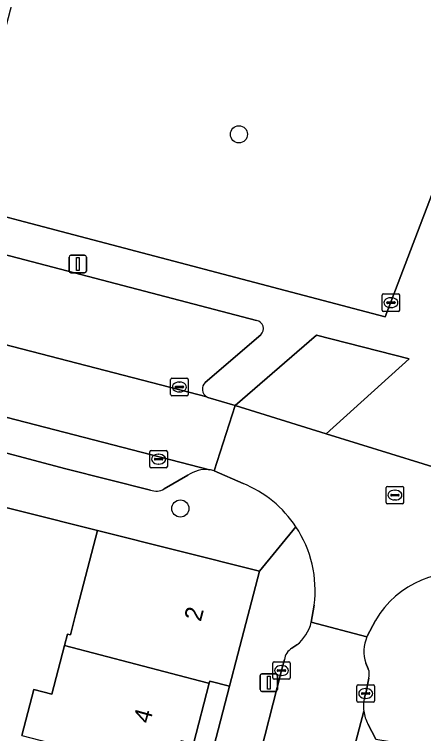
# Model space of a CAD drawing. Extents: x 163683 to 164494, y 382709 to 383872.
# Drawn here: x 164180.51 to 164203.92, y 383184.47 to 383225.65 of the extents above; entities that cross this region are included whole.
import ezdxf

# ---------------------------------------------------------------- set-up
doc = ezdxf.new("R2010")
doc.units = 0
for name, color, linetype in [('IMGEO_Boom', 7, 'Continuous'), ('IMGEO_Erf', 7, 'Continuous'), ('IMGEO_Groenvoorziening', 7, 'Continuous'), ('IMGEO_Kolk', 7, 'Continuous'), ('IMGEO_Lichtmast', 7, 'Continuous'), ('IMGEO_Muur', 7, 'Continuous'), ('IMGEO_Pand', 7, 'Continuous'), ('IMGEO_Pand_nummerreeks', 7, 'Continuous'), ('IMGEO_Parkeervlak_open', 7, 'Continuous'), ('IMGEO_Rijbaan_lokaal_open', 7, 'Continuous'), ('IMGEO_Rioolput', 7, 'Continuous'), ('IMGEO_Voetpad_open', 7, 'Continuous')]:
    doc.layers.add(name, color=color, linetype=linetype)

msp = doc.modelspace()

# ---------------------------------------------------------------- linework, layer by layer
at = {"layer": 'IMGEO_Boom'}
for centre in [(164193.357, 383218.784), (164190.006, 383197.355)]:
    msp.add_circle(centre, 0.489, dxfattribs=at)
at = {"layer": 'IMGEO_Erf'}
msp.add_lwpolyline([(164180.944, 383184.366), (164181.629, 383187), (164182.658, 383186.732), (164183.379, 383189.505), (164183.551, 383190.167), (164183.712, 383190.125), (164184.009, 383191.261), (164185.275, 383196.098), (164176.583, 383198.281), (164174.876, 383191.699), (164171.766, 383192.505), (164171.003, 383189.379), (164174.475, 383188.478), (164173.885, 383186.203), (164172.661, 383181.485)], dxfattribs=at)
msp.add_lwpolyline([(164192.826, 383187.181), (164191.684, 383187.478), (164191.651, 383187.35), (164190.752, 383183.877), (164190.046, 383184.06), (164189.546, 383182.128), (164189.063, 383180.265), (164189.769, 383180.082), (164188.78, 383176.264), (164187.826, 383172.58), (164187.12, 383172.763), (164186.601, 383170.759), (164186.138, 383168.968), (164186.844, 383168.785), (164185.839, 383164.904), (164184.903, 383161.292), (164184.197, 383161.475), (164183.658, 383159.39), (164183.215, 383157.68), (164183.921, 383157.497), (164182.985, 383153.885), (164184.107, 383153.593)], close=True, dxfattribs=at)
at = {"layer": 'IMGEO_Groenvoorziening'}
msp.add_lwpolyline([(164211.56, 383234.158), (164211.902, 383235.056), (164184.544, 383242.181), (164182.325, 383233.76), (164178.067, 383217.602), (164176.82, 383217.925), (164176.086, 383215.093), (164178.697, 383214.405), (164180.721, 383213.871), (164201.717, 383208.336), (164202.06, 383209.236)], close=True, dxfattribs=at)
at = {"layer": 'IMGEO_Kolk'}
for p, q in [((164201.553, 383208.718), (164201.553, 383209.57)), ((164201.628, 383209.644), (164202.48, 383209.644)), ((164202.041, 383209.424), (164202.066, 383209.424)), ((164202.554, 383209.57), (164202.554, 383208.718)), ((164201.812, 383209.138), (164201.812, 383209.15)), ((164202.25, 383209.101), (164201.852, 383209.101)), ((164201.855, 383209.187), (164202.253, 383209.187)), ((164202.064, 383208.864), (164202.039, 383208.864)), ((164202.296, 383209.15), (164202.296, 383209.138)), ((164202.48, 383208.644), (164201.628, 383208.644)), ((164189.452, 383203.888), (164189.452, 383204.74)), ((164189.527, 383204.814), (164190.379, 383204.814)), ((164190.453, 383204.74), (164190.453, 383203.888)), ((164189.711, 383204.308), (164189.711, 383204.32)), ((164189.754, 383204.357), (164190.152, 383204.357)), ((164189.94, 383204.594), (164189.965, 383204.594)), ((164190.195, 383204.32), (164190.195, 383204.308)), ((164190.149, 383204.271), (164189.751, 383204.271)), ((164189.963, 383204.034), (164189.938, 383204.034)), ((164190.379, 383203.814), (164189.527, 383203.814)), ((164188.263, 383199.758), (164188.263, 383200.61)), ((164188.338, 383200.684), (164189.19, 383200.684)), ((164189.264, 383200.61), (164189.264, 383199.758)), ((164188.565, 383200.227), (164188.963, 383200.227)), ((164188.751, 383200.464), (164188.776, 383200.464)), ((164188.522, 383200.178), (164188.522, 383200.19)), ((164188.96, 383200.141), (164188.562, 383200.141)), ((164188.774, 383199.904), (164188.749, 383199.904)), ((164189.006, 383200.19), (164189.006, 383200.178)), ((164189.19, 383199.684), (164188.338, 383199.684)), ((164195.29, 383187.652), (164195.29, 383188.504)), ((164195.365, 383188.578), (164196.217, 383188.578)), ((164195.778, 383188.358), (164195.803, 383188.358)), ((164196.291, 383188.504), (164196.291, 383187.652)), ((164195.549, 383188.072), (164195.549, 383188.084)), ((164195.987, 383188.035), (164195.589, 383188.035)), ((164195.592, 383188.121), (164195.99, 383188.121)), ((164196.033, 383188.084), (164196.033, 383188.072)), ((164196.217, 383187.578), (164195.365, 383187.578)), ((164195.801, 383187.798), (164195.776, 383187.798)), ((164200.109, 383186.338), (164200.109, 383187.19)), ((164200.184, 383187.264), (164201.036, 383187.264)), ((164200.597, 383187.044), (164200.622, 383187.044)), ((164201.11, 383187.19), (164201.11, 383186.338)), ((164200.368, 383186.758), (164200.368, 383186.77)), ((164200.806, 383186.721), (164200.408, 383186.721)), ((164200.411, 383186.807), (164200.809, 383186.807)), ((164200.852, 383186.77), (164200.852, 383186.758)), ((164201.036, 383186.264), (164200.184, 383186.264)), ((164200.62, 383186.484), (164200.595, 383186.484))]:
    msp.add_line(p, q, dxfattribs=at)
for points in [[(164201.553, 383208.718), (164201.553, 383209.57)], [(164201.628, 383209.644), (164202.48, 383209.644)], [(164202.554, 383209.57), (164202.554, 383208.718)], [(164202.48, 383208.644), (164201.628, 383208.644)], [(164189.452, 383203.888), (164189.452, 383204.74)], [(164189.527, 383204.814), (164190.379, 383204.814)], [(164190.453, 383204.74), (164190.453, 383203.888)], [(164190.379, 383203.814), (164189.527, 383203.814)], [(164188.263, 383199.758), (164188.263, 383200.61)], [(164188.338, 383200.684), (164189.19, 383200.684)], [(164189.264, 383200.61), (164189.264, 383199.758)], [(164189.19, 383199.684), (164188.338, 383199.684)], [(164195.29, 383187.652), (164195.29, 383188.504)], [(164195.365, 383188.578), (164196.217, 383188.578)], [(164196.291, 383188.504), (164196.291, 383187.652)], [(164196.217, 383187.578), (164195.365, 383187.578)], [(164200.109, 383186.338), (164200.109, 383187.19)], [(164200.184, 383187.264), (164201.036, 383187.264)], [(164201.11, 383187.19), (164201.11, 383186.338)], [(164201.036, 383186.264), (164200.184, 383186.264)]]:
    msp.add_lwpolyline(points, dxfattribs=at)
for centre, radius, start, end in [((164201.63, 383209.568), 0.0765, 91.552, 178.448), ((164201.63, 383209.568), 0.0765, 91.552, 178.448), ((164202.478, 383209.568), 0.0765, 1.552, 88.448), ((164202.478, 383209.568), 0.0765, 1.552, 88.448), ((164201.852, 383209.147), 0.0403, 85.8775, 175.7526), ((164201.849, 383209.137), 0.0366, 178.938, 274.7102), ((164202.253, 383209.144), 0.043, 264.8664, 352.4533), ((164202.257, 383209.149), 0.0386, 1.7309, 96.639), ((164201.63, 383208.72), 0.0765, 181.552, 268.448), ((164201.63, 383208.72), 0.0765, 181.552, 268.448), ((164202.478, 383208.72), 0.0765, 271.552, 358.448), ((164202.478, 383208.72), 0.0765, 271.552, 358.448), ((164189.529, 383204.738), 0.0765, 91.552, 178.448), ((164189.529, 383204.738), 0.0765, 91.552, 178.448), ((164190.377, 383204.738), 0.0765, 1.552, 88.448), ((164190.377, 383204.738), 0.0765, 1.552, 88.448), ((164189.751, 383204.317), 0.0403, 85.8775, 175.7526), ((164190.156, 383204.319), 0.0386, 1.7309, 96.639), ((164189.748, 383204.307), 0.0366, 178.938, 274.7102), ((164190.152, 383204.314), 0.043, 264.8664, 352.4533), ((164189.529, 383203.89), 0.0765, 181.552, 268.448), ((164189.529, 383203.89), 0.0765, 181.552, 268.448), ((164190.377, 383203.89), 0.0765, 271.552, 358.448), ((164190.377, 383203.89), 0.0765, 271.552, 358.448), ((164188.34, 383200.608), 0.0765, 91.552, 178.448), ((164188.34, 383200.608), 0.0765, 91.552, 178.448), ((164189.188, 383200.608), 0.0765, 1.552, 88.448), ((164189.188, 383200.608), 0.0765, 1.552, 88.448), ((164188.562, 383200.187), 0.0403, 85.8775, 175.7526), ((164188.967, 383200.189), 0.0386, 1.7309, 96.639), ((164188.559, 383200.177), 0.0366, 178.938, 274.7102), ((164188.963, 383200.184), 0.043, 264.8664, 352.4533), ((164188.34, 383199.76), 0.0765, 181.552, 268.448), ((164188.34, 383199.76), 0.0765, 181.552, 268.448), ((164189.188, 383199.76), 0.0765, 271.552, 358.448), ((164189.188, 383199.76), 0.0765, 271.552, 358.448), ((164195.367, 383188.502), 0.0765, 91.552, 178.448), ((164195.367, 383188.502), 0.0765, 91.552, 178.448), ((164196.215, 383188.502), 0.0765, 1.552, 88.448), ((164196.215, 383188.502), 0.0765, 1.552, 88.448), ((164195.589, 383188.081), 0.0403, 85.8775, 175.7526), ((164195.586, 383188.071), 0.0366, 178.938, 274.7102), ((164195.99, 383188.078), 0.043, 264.8664, 352.4533), ((164195.994, 383188.083), 0.0386, 1.7309, 96.639), ((164195.367, 383187.654), 0.0765, 181.552, 268.448), ((164195.367, 383187.654), 0.0765, 181.552, 268.448), ((164196.215, 383187.654), 0.0765, 271.552, 358.448), ((164196.215, 383187.654), 0.0765, 271.552, 358.448), ((164200.186, 383187.188), 0.0765, 91.552, 178.448), ((164200.186, 383187.188), 0.0765, 91.552, 178.448), ((164201.034, 383187.188), 0.0765, 1.552, 88.448), ((164201.034, 383187.188), 0.0765, 1.552, 88.448), ((164200.408, 383186.767), 0.0403, 85.8775, 175.7526), ((164200.405, 383186.757), 0.0366, 178.938, 274.7102), ((164200.809, 383186.764), 0.043, 264.8664, 352.4533), ((164200.813, 383186.769), 0.0386, 1.7309, 96.639), ((164200.186, 383186.34), 0.0765, 181.552, 268.448), ((164200.186, 383186.34), 0.0765, 181.552, 268.448), ((164201.034, 383186.34), 0.0765, 271.552, 358.448), ((164201.034, 383186.34), 0.0765, 271.552, 358.448)]:
    msp.add_arc(centre, radius, start, end, dxfattribs=at)
for centre, major_axis, ratio, start_param, end_param in [((164202.04, 383209.144), (-0.387, 0.002), 0.722429, 4.712389, 7.853982), ((164202.065, 383209.144), (-0.39, 0.002), 0.717154, 1.570796, 4.712389), ((164189.939, 383204.314), (-0.387, 0.002), 0.722429, 4.712389, 7.853982), ((164189.964, 383204.314), (-0.39, 0.002), 0.717154, 1.570796, 4.712389), ((164188.75, 383200.184), (-0.387, 0.002), 0.722429, 4.712389, 7.853982), ((164188.775, 383200.184), (-0.39, 0.002), 0.717154, 1.570796, 4.712389), ((164195.777, 383188.078), (-0.387, 0.002), 0.722429, 4.712389, 7.853982), ((164195.802, 383188.078), (-0.39, 0.002), 0.717154, 1.570796, 4.712389), ((164200.596, 383186.764), (-0.387, 0.002), 0.722429, 4.712389, 7.853982), ((164200.621, 383186.764), (-0.39, 0.002), 0.717154, 1.570796, 4.712389)]:
    msp.add_ellipse(centre, major_axis=major_axis, ratio=ratio, start_param=start_param, end_param=end_param, dxfattribs=at)
at = {"layer": 'IMGEO_Lichtmast'}
for p, q in [((164183.639, 383210.956), (164183.639, 383211.756)), ((164183.639, 383211.756), (164183.639, 383210.956)), ((164183.739, 383211.856), (164184.529, 383211.856)), ((164184.529, 383211.856), (164183.739, 383211.856)), ((164184.629, 383211.756), (164184.629, 383210.956)), ((164184.629, 383210.956), (164184.629, 383211.756)), ((164184.529, 383210.856), (164183.739, 383210.856)), ((164183.739, 383210.856), (164184.529, 383210.856)), ((164194.667, 383187.885), (164195.457, 383187.885)), ((164195.457, 383187.885), (164194.667, 383187.885)), ((164194.567, 383186.985), (164194.567, 383187.785)), ((164194.567, 383187.785), (164194.567, 383186.985)), ((164195.557, 383187.785), (164195.557, 383186.985)), ((164195.557, 383186.985), (164195.557, 383187.785)), ((164195.457, 383186.885), (164194.667, 383186.885)), ((164194.667, 383186.885), (164195.457, 383186.885))]:
    msp.add_line(p, q, dxfattribs=at)
for points in [[(164184.059, 383211.731), (164184.209, 383211.731), (164184.209, 383210.981), (164184.059, 383210.981), (164184.059, 383211.731)], [(164194.987, 383187.76), (164195.137, 383187.76), (164195.137, 383187.01), (164194.987, 383187.01), (164194.987, 383187.76)]]:
    msp.add_lwpolyline(points, dxfattribs=at)
for centre, start, end in [((164183.739, 383211.756), 90, 180), ((164183.739, 383211.756), 90, 180), ((164184.529, 383211.756), 0, 90), ((164184.529, 383211.756), 360, 90), ((164183.739, 383210.956), 180, 270), ((164183.739, 383210.956), 180, 270), ((164184.529, 383210.956), 270, 0), ((164184.529, 383210.956), 270, 0), ((164194.667, 383187.785), 90, 180), ((164194.667, 383187.785), 90, 180), ((164195.457, 383187.785), 0, 90), ((164195.457, 383187.785), 360, 90), ((164194.667, 383186.985), 180, 270), ((164194.667, 383186.985), 180, 270), ((164195.457, 383186.985), 270, 0), ((164195.457, 383186.985), 270, 0)]:
    msp.add_arc(centre, 0.1, start, end, dxfattribs=at)
at = {"layer": 'IMGEO_Muur'}
msp.add_lwpolyline([(164176.583, 383198.281), (164185.275, 383196.098)], dxfattribs=at)
at = {"layer": 'IMGEO_Pand'}
for points in [[(164183.379, 383189.505), (164191.535, 383187.38), (164191.651, 383187.35), (164191.684, 383187.478), (164192.826, 383187.181), (164193.301, 383189.011), (164194.537, 383193.772), (164185.275, 383196.098), (164184.009, 383191.261), (164183.712, 383190.125), (164183.551, 383190.167)], [(164180.944, 383184.366), (164189.546, 383182.128), (164190.046, 383184.06), (164190.752, 383183.877), (164191.651, 383187.35), (164191.535, 383187.38), (164183.379, 383189.505), (164182.658, 383186.732), (164181.629, 383187)]]:
    msp.add_lwpolyline(points, close=True, dxfattribs=at)
at = {"layer": 'IMGEO_Parkeervlak_open'}
for points in [[(164194.367, 383208.132), (164180.308, 383211.798), (164179.296, 383212.06)], [(164174.565, 383208.139), (164191.519, 383203.748)], [(164191.428, 383204.572), (164194.606, 383207.31)], [(164200.503, 383185.752), (164195.035, 383165.03)], [(164201.195, 383184.141), (164200.736, 383185.025)]]:
    msp.add_lwpolyline(points, dxfattribs=at)
msp.add_lwpolyline([(164193.144, 383203.259), (164198.344, 383201.637), (164203.1, 383205.927), (164197.787, 383207.289)], close=True, dxfattribs=at)
for centre, radius, start, end in [((164194.274, 383207.659), 0.482, 313.5755, 78.8485), ((164191.781, 383204.194), 0.517, 133.058, 239.5461), ((164202.635, 383186.034), 2.15, 187.5445, 207.9963)]:
    msp.add_arc(centre, radius, start, end, dxfattribs=at)
at = {"layer": 'IMGEO_Rijbaan_lokaal_open'}
for points in [[(164191.674, 383199.573), (164137.37, 383213.628), (164065.47, 383232.191)], [(164065.47, 383232.191), (164137.37, 383213.628), (164191.674, 383199.573)], [(164067.443, 383229.643), (164078.076, 383226.898), (164083.857, 383225.406), (164123.682, 383215.09), (164133.127, 383212.643), (164172.83, 383202.406), (164178.631, 383200.91), (164182.52, 383199.875), (164183.453, 383199.638), (164188.301, 383198.414)], [(164191.936, 383199.519), (164193.144, 383203.259), (164191.577, 383203.719), (164191.548, 383203.733), (164191.519, 383203.748), (164174.565, 383208.139)], [(164212.176, 383197.307), (164211.291, 383197.629), (164198.344, 383201.637), (164193.144, 383203.259), (164191.936, 383199.519), (164193.591, 383198.789)], [(164189.075, 383198.48), (164190.439, 383199.257)], [(164197.667, 383191.827), (164197.5, 383190.84), (164200.68, 383190.002), (164200.702, 383190.05), (164201.176, 383190.951)], [(164200.68, 383190.002), (164197.5, 383190.84)], [(164196.666, 383189.542), (164196.387, 383189.35)], [(164195.962, 383188.713), (164195.791, 383188.078), (164194.358, 383182.464), (164189.313, 383162.614), (164185.499, 383148.358), (164185.032, 383146.554)], [(164200.761, 383188.179), (164200.622, 383188.506)], [(164200.542, 383186.562), (164200.61, 383186.764), (164200.79, 383187.637)], [(164185.239, 383144.22), (164185.117, 383143.761), (164188.959, 383142.625), (164189.357, 383144.074), (164193.665, 383159.724), (164194.577, 383163.198), (164195.035, 383165.03), (164200.503, 383185.752)]]:
    msp.add_lwpolyline(points, dxfattribs=at)
for centre, radius, start, end in [((164191.457, 383197.851), 1.736, 82.8053, 125.8994), ((164191.451, 383197.83), 1.757, 73.9877, 82.7204), ((164191.101, 383192.656), 6.619, 33.4661, 67.9036), ((164188.621, 383199.232), 0.878, 248.6214, 301.1264), ((164191.107, 383192.659), 6.612, 352.77, 33.4714), ((164205.874, 383188.236), 5.426, 74.9953, 149.9735), ((164195.189, 383191.408), 2.379, 308.3597, 346.1966), ((164202.546, 383189.181), 2.039, 156.2366, 199.3229), ((164196.818, 383188.602), 0.864, 119.9723, 172.6061), ((164199.919, 383187.862), 0.9, 345.5048, 20.6207), ((164202.426, 383186.065), 1.948, 165.2314, 189.2555)]:
    msp.add_arc(centre, radius, start, end, dxfattribs=at)
at = {"layer": 'IMGEO_Rioolput'}
for p, q in [((164201.782, 383197.698), (164201.782, 383198.55)), ((164201.857, 383198.624), (164202.709, 383198.624)), ((164202.783, 383198.55), (164202.783, 383197.698)), ((164202.084, 383198.167), (164202.482, 383198.167)), ((164202.27, 383198.404), (164202.295, 383198.404)), ((164202.041, 383198.118), (164202.041, 383198.13)), ((164202.479, 383198.081), (164202.081, 383198.081)), ((164202.293, 383197.844), (164202.268, 383197.844)), ((164202.525, 383198.13), (164202.525, 383198.118)), ((164202.709, 383197.624), (164201.857, 383197.624))]:
    msp.add_line(p, q, dxfattribs=at)
for points in [[(164201.782, 383197.698), (164201.782, 383198.55)], [(164201.857, 383198.624), (164202.709, 383198.624)], [(164202.783, 383198.55), (164202.783, 383197.698)], [(164202.709, 383197.624), (164201.857, 383197.624)]]:
    msp.add_lwpolyline(points, dxfattribs=at)
for centre, radius, start, end in [((164201.859, 383198.548), 0.0765, 91.552, 178.448), ((164201.859, 383198.548), 0.0765, 91.552, 178.448), ((164202.707, 383198.548), 0.0765, 1.552, 88.448), ((164202.707, 383198.548), 0.0765, 1.552, 88.448), ((164202.081, 383198.127), 0.0403, 85.8775, 175.7526), ((164202.486, 383198.129), 0.0386, 1.7309, 96.639), ((164202.078, 383198.117), 0.0366, 178.938, 274.7102), ((164202.482, 383198.124), 0.043, 264.8664, 352.4533), ((164201.859, 383197.7), 0.0765, 181.552, 268.448), ((164201.859, 383197.7), 0.0765, 181.552, 268.448), ((164202.707, 383197.7), 0.0765, 271.552, 358.448), ((164202.707, 383197.7), 0.0765, 271.552, 358.448)]:
    msp.add_arc(centre, radius, start, end, dxfattribs=at)
for centre, major_axis, ratio, start_param, end_param in [((164202.269, 383198.124), (-0.387, 0.002), 0.722429, 4.712389, 7.853982), ((164202.294, 383198.124), (-0.39, 0.002), 0.717154, 1.570796, 4.712389)]:
    msp.add_ellipse(centre, major_axis=major_axis, ratio=ratio, start_param=start_param, end_param=end_param, dxfattribs=at)
at = {"layer": 'IMGEO_Voetpad_open'}
for points in [[(164211.56, 383234.158), (164202.06, 383209.236), (164201.717, 383208.336), (164180.721, 383213.871), (164178.697, 383214.405), (164176.086, 383215.093), (164174.958, 383210.745), (164163.56, 383213.701), (164165.194, 383220.005), (164164.803, 383220.106), (164165.555, 383223.008)], [(164188.301, 383198.414), (164183.453, 383199.638), (164182.52, 383199.875), (164178.631, 383200.91), (164178.343, 383199.742), (164172.528, 383201.19), (164172.83, 383202.406), (164133.127, 383212.643)], [(164179.296, 383212.06), (164180.308, 383211.798), (164194.367, 383208.132)], [(164131.207, 383210.146), (164165.211, 383201.212), (164165.276, 383201.461), (164171.86, 383199.754), (164171.782, 383199.454), (164173.473, 383199.087), (164173.798, 383199.003), (164176.279, 383198.36), (164176.583, 383198.281), (164185.275, 383196.098), (164194.537, 383193.772), (164196.623, 383196.306)], [(164194.606, 383207.31), (164191.428, 383204.572)], [(164191.519, 383203.748), (164191.548, 383203.733), (164191.577, 383203.719), (164193.144, 383203.259), (164197.787, 383207.289), (164203.1, 383205.927), (164198.344, 383201.637), (164211.291, 383197.629), (164212.176, 383197.307), (164217.636, 383195.693), (164217.81, 383195.654)], [(164193.591, 383198.789), (164191.936, 383199.519)], [(164190.439, 383199.257), (164189.075, 383198.48)], [(164196.623, 383196.306), (164194.537, 383193.772), (164193.301, 383189.011), (164192.826, 383187.181), (164184.107, 383153.593), (164184.067, 383153.438), (164182.395, 383147.001), (164181.718, 383144.288)], [(164197.5, 383190.84), (164197.667, 383191.827)], [(164201.176, 383190.951), (164200.702, 383190.05), (164200.68, 383190.002)], [(164196.387, 383189.35), (164196.666, 383189.542)], [(164194.358, 383182.464), (164195.791, 383188.078), (164195.962, 383188.713)], [(164200.622, 383188.506), (164200.761, 383188.179)], [(164200.79, 383187.637), (164200.61, 383186.764), (164200.542, 383186.562)], [(164200.736, 383185.025), (164201.195, 383184.141), (164203.756, 383183.734)]]:
    msp.add_lwpolyline(points, dxfattribs=at)
for centre, radius, start, end in [((164194.274, 383207.659), 0.482, 313.5755, 78.8485), ((164191.781, 383204.194), 0.517, 133.058, 239.5461), ((164191.457, 383197.851), 1.736, 82.8053, 125.8994), ((164191.451, 383197.83), 1.757, 73.9877, 82.7204), ((164191.101, 383192.656), 6.619, 33.4661, 67.9036), ((164188.621, 383199.232), 0.878, 248.6214, 301.1264), ((164191.107, 383192.659), 6.612, 352.77, 33.4714), ((164205.874, 383188.236), 5.426, 74.9953, 149.9735), ((164195.189, 383191.408), 2.379, 308.3597, 346.1966), ((164202.546, 383189.181), 2.039, 156.2366, 199.3229), ((164196.818, 383188.602), 0.864, 119.9723, 172.6061), ((164199.919, 383187.862), 0.9, 345.5048, 20.6207), ((164202.426, 383186.065), 1.948, 165.2314, 189.2555), ((164202.635, 383186.034), 2.15, 187.5445, 207.9963)]:
    msp.add_arc(centre, radius, start, end, dxfattribs=at)

# ---------------------------------------------------------------- texts
at = {"layer": 'IMGEO_Pand_nummerreeks'}
for s, rotation, p in [('2', 75.4474, (164191.173, 383190.841)), ('4', 74.4785, (164188.258, 383185))]:
    msp.add_text(s, height=1, rotation=rotation, dxfattribs=at).set_placement(p)

doc.saveas('drawing.dxf')
